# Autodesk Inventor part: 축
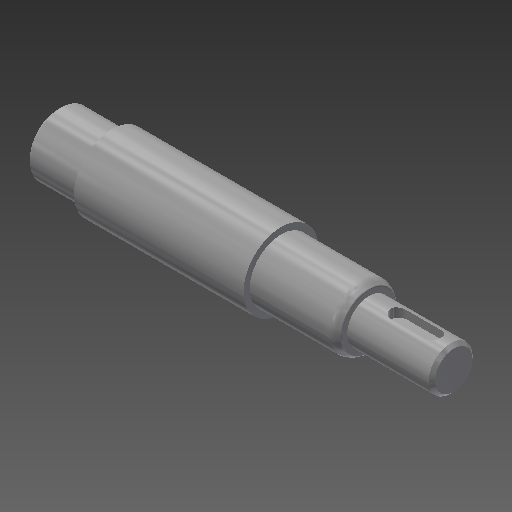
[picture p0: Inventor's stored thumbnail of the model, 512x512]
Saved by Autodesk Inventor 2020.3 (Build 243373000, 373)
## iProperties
Created: 2016-06
Part Number: 축
Material: 강철, 연강
Document SubType Name: Modeling
Designer: mduedu
Density: 7.86 g/cm^3
Appearance: 강철
Author: mduedu
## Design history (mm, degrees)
sketch "스케치1"
  geometry: L1 (-63, 0)-(63, 0); L2 (-63, 0)-(-63, 10); L3 (-63, 10)-(-46, 10); L4 (-46, 10)-(-46, 12); L5 (-46, 12)-(8, 12); L6 (8, 12)-(8, 10); L7 (8, 10)-(36, 10); L8 (36, 10)-(36, 7); L9 (36, 7)-(63, 7); L10 (63, 7)-(63, 0); 2 further points
  constraints: 20 end point, 5 parallel, 2 perpendicular, 1 coincident, 1 collinear, 1 horizontal, 1 midpoint, 1 vertical
  dimensions: "d0" = 126 distance of L1.start L1.end; "d2" = 14 diameter of L9 L1; "d3" = 20 diameter of L7 L1; "d4" = 24 diameter of L5 L1; "d5" = 20 diameter of L3 L1; "d6" = 17 distance of L2.end L3.end; "d7" = 27 distance of L8.end L9.end; "d8" = 55 distance from line of L5.end L10
revolve "회전1" sketch "스케치1" stored, may be unused: angle "d9" = 90 deg
sketch "스케치5"
  geometry: L1 (63, 10)-(63, -10) reference; L2 (63, -10)-(46, -10) reference; L3 (46, -10)-(46, -12) reference; L4 (46, -12)-(-8, -12) reference; L5 (-8, -12)-(-8, -10) reference; L6 (-8, -10)-(-36, -10) reference; L7 (-36, -10)-(-36, -7) reference; L8 (-36, -7)-(-63, -7) reference; L9 (-63, -7)-(-63, 7) reference; L10 (-63, 7)-(-36, 7) reference; L11 (-36, 7)-(-36, 10) reference; L12 (-36, 10)-(-8, 10) reference; L13 (-8, 10)-(-8, 12) reference; L14 (-8, 12)-(46, 12) reference; L15 (46, 12)-(46, 10) reference; L16 (46, 10)-(63, 10) reference; L17 (-63, 0)-(63, 0); L18 (-36, 8.85)-(-34.008, 10); L19 (-34.008, 10)-(-36, 10); L20 (-36, 10)-(-36, 8.85); 1 further point
  constraints: 8 end point, 2 midpoint, 2 point on line, 1 collinear, 1 perpendicular
  dimensions: "d36" = 17.7 diameter of L18.start L17; "d37" = 30 deg angle of L12 L18
revolve "회전3" sketch "스케치5" stored, may be unused: angle "d38" = 90 deg
fillet "모깎기1" dims "d13" = 4, "d39" = 0.5
node "작업 평면1"
sketch "스케치2"
  geometry: L1 (-4, 2.5)-(7, 2.5); L2 (7, -2.5)-(-4, -2.5); L3 (-4, 0)-(7, 0); L4 (-13.5, 8.561)-(-13.5, -8.561) reference; A1 r 2.5 centre (-4, 0) between (-4, 2.5) and (-4, -2.5); A2 r 2.5 centre (7, 0) between (7, -2.5) and (7, 2.5); 1 further point
  constraints: 6 end point, 4 point on circle, 3 tangent, 2 centre point, 2 parallel, 1 horizontal, 1 horizontal alignment
  dimensions: "d15" = 5 distance between parallel lines of L2 L1; "d16" = 16 dimension on A2 A1; "d40" = 7 distance edge to line of A1 L4
extrude "돌출1" cut sketch "스케치2" distance "d17" = 3; taper "d18" = 0 deg
chamfer "모따기2" distance "d19" = 1; stored, may be unused: second distance "d20" = 2, angle "d21" = 30 deg
sketch "스케치3"
  geometry: L1 (-36, -7)-(-62, -7) reference; L2 (-63, -6)-(-63, 6) reference; L3 (-39.5, -7)-(-41, -5.5); L4 (-41, -5.5)-(-41, -7); L5 (-39.5, -7)-(-41, -7); 1 further point
  constraints: 6 end point, 2 point on line, 1 collinear, 1 vertical
  dimensions: "d22" = 45 deg angle of L4 L3; "d23" = 22 distance between parallel lines of L2 L4; "d24" = 3 diameter of L3.start L4
revolve "회전2" stored, may be unused: angle "d25" = 90 deg
node "작업점1"
sketch "스케치4"
  geometry: 1 further point
hole "구멍1" sketch "스케치4" at (0, 0) diameter "d26" = 3.242; stored, may be unused: countersink angle "d30" = 90 deg, drill point angle "d32" = 120 deg; dims "d27" = 8, "d28" = 4, "d29" = 2, "d31" = 11
chamfer "모따기3" distance "d33" = 2; stored, may be unused: second distance "d34" = 2, angle "d35" = 30 deg
node "솔리드1"
node "절단 모서리 투영1"
